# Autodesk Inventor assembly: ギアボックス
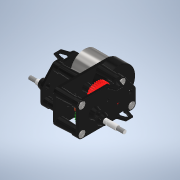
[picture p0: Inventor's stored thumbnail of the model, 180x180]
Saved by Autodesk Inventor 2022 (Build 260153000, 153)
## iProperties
Created: 2024-10
Part Number: ギアボックス
Document SubType Name: Assembly
Designer: shimizu
Author: shimizu
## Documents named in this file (11)
- C:\Users\shimizu\Documents\卒論2024\3DCAD\ギアボックス\組立図\ギアボックス.iam
- C:\Users\shimizu\Documents\卒論2024\3DCAD\ギアボックス\部品図\ギアケースA（中央）.ipt
- C:\Users\shimizu\Documents\卒論2024\3DCAD\ギアボックス\部品図\モーター.ipt
- C:\Users\shimizu\Documents\卒論2024\3DCAD\ギアボックス\部品図\ギアケースC（モーターヘッド側）.ipt
- C:\Users\shimizu\Documents\卒論2024\3DCAD\ギアボックス\部品図\ギアジョイント.ipt
- C:\Users\shimizu\Documents\卒論2024\3DCAD\ギアボックス\部品図\4mmシャフト.ipt
- C:\Users\shimizu\Documents\卒論2024\3DCAD\ギアボックス\部品図\ギアケースB（ギア側）.ipt
- C:\Users\shimizu\Documents\卒論2024\3DCAD\ギアボックス\部品図\38Tギア.ipt
- C:\Users\shimizu\Documents\卒論2024\3DCAD\ギアボックス\部品図\34T-12Tギア.iam
- C:\Users\shimizu\Documents\卒論2024\3DCAD\ギアボックス\部品図\10Tギア.ipt
- C:\Users\shimizu\Documents\卒論2024\3DCAD\ギアボックス\部品図\ねじ.ipt
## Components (17 placed, 9 different names)
1. ギアケースA（中央）:1 — メイト:1, メイト:2, メイト:3, メイト:4, メイト:5, メイト:6, メイト:7, メイト:8, メイト:9, メイト:10, メイト:29, メイト:30, メイト:31, メイト:32, 角度:2
2. モーター:1 — メイト:1, メイト:2, 角度:1, メイト:33
3. ギアケースC（モーターヘッド側）:1 — メイト:3, メイト:4, メイト:5, 角度:1, メイト:42, メイト:43, メイト:44, メイト:45, メイト:46, メイト:47
4. ギアジョイント:1 — メイト:6, メイト:7, リジッド:1, メイト:26, メイト:27
5. 4mmシャフト:1 — リジッド:1, メイト:28
6. ギアケースB（ギア側）:1 — メイト:8, メイト:9, メイト:10, メイト:34, メイト:35, メイト:36, メイト:37, メイト:38, メイト:39, メイト:40, メイト:41
7. 平歯車1:1 — メイト:26, メイト:27, メイト:28, 回転:1
8. 34T-12Tギア:1 [sub-assembly] — メイト:31, メイト:32, 回転:1, 回転:2
9. 34T-12Tギア:2 [sub-assembly] — メイト:29, メイト:30, フラッシュ:2, 回転:2, 回転:3
10. 平歯車1:2 — フラッシュ:2, メイト:33, 回転:3, 角度:2
11. JIS B 1111 M3x8:1 — メイト:34, メイト:35
12. JIS B 1111 M3x8:2 — メイト:46, メイト:47
13. JIS B 1111 M3x8:3 — メイト:36, メイト:37
14. JIS B 1111 M3x8:4 — メイト:40, メイト:41
15. JIS B 1111 M3x8:5 — メイト:38, メイト:39
16. JIS B 1111 M3x8:6 — メイト:44, メイト:45
17. JIS B 1111 M3x8:7 — メイト:42, メイト:43
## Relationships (39: Mate 32, RelateRotation 3, Angle 2, WeldJoint 1, Flush 1)
- メイト:1 [Mate]: ギアケースA（中央）:1 ↔ モーター:1
- メイト:2 [Mate]: ギアケースA（中央）:1 ↔ モーター:1
- メイト:3 [Mate]: ギアケースA（中央）:1 ↔ ギアケースC（モーターヘッド側）:1
- メイト:4 [Mate]: ギアケースA（中央）:1 ↔ ギアケースC（モーターヘッド側）:1
- メイト:5 [Mate]: ギアケースA（中央）:1 ↔ ギアケースC（モーターヘッド側）:1
- 角度:1 [Angle]: モーター:1 ↔ ギアケースC（モーターヘッド側）:1
- メイト:6 [Mate]: ギアケースA（中央）:1 ↔ ギアジョイント:1
- メイト:7 [Mate]: ギアケースA（中央）:1 ↔ ギアジョイント:1
- リジッド:1 [WeldJoint]: ギアジョイント:1 ↔ 4mmシャフト:1
- メイト:8 [Mate]: ギアケースA（中央）:1 ↔ ギアケースB（ギア側）:1
- メイト:9 [Mate]: ギアケースA（中央）:1 ↔ ギアケースB（ギア側）:1
- メイト:10 [Mate]: ギアケースA（中央）:1 ↔ ギアケースB（ギア側）:1
- メイト:26 [Mate]: ギアジョイント:1 ↔ 平歯車1:1
- メイト:27 [Mate]: ギアジョイント:1 ↔ 平歯車1:1
- メイト:28 [Mate]: 4mmシャフト:1 ↔ 平歯車1:1
- メイト:29 [Mate]: ギアケースA（中央）:1 ↔ 34T-12Tギア:2
- メイト:30 [Mate]: ギアケースA（中央）:1 ↔ 34T-12Tギア:2
- メイト:31 [Mate]: ギアケースA（中央）:1 ↔ 34T-12Tギア:1
- メイト:32 [Mate]: ギアケースA（中央）:1 ↔ 34T-12Tギア:1
- フラッシュ:2 [Flush]: 34T-12Tギア:2 ↔ 平歯車1:2
- メイト:33 [Mate]: モーター:1 ↔ 平歯車1:2
- 回転:1 [RelateRotation]: 平歯車1:1 ↔ 34T-12Tギア:1
- 回転:2 [RelateRotation]: 34T-12Tギア:1 ↔ 34T-12Tギア:2
- 回転:3 [RelateRotation]: 34T-12Tギア:2 ↔ 平歯車1:2
- 角度:2 [Angle]: ギアケースA（中央）:1 ↔ 平歯車1:2
- メイト:34 [Mate]: ギアケースB（ギア側）:1 ↔ JIS B 1111 M3x8:1
- メイト:35 [Mate]: ギアケースB（ギア側）:1 ↔ JIS B 1111 M3x8:1
- メイト:36 [Mate]: ギアケースB（ギア側）:1 ↔ JIS B 1111 M3x8:3
- メイト:37 [Mate]: ギアケースB（ギア側）:1 ↔ JIS B 1111 M3x8:3
- メイト:38 [Mate]: ギアケースB（ギア側）:1 ↔ JIS B 1111 M3x8:5
- メイト:39 [Mate]: ギアケースB（ギア側）:1 ↔ JIS B 1111 M3x8:5
- メイト:40 [Mate]: ギアケースB（ギア側）:1 ↔ JIS B 1111 M3x8:4
- メイト:41 [Mate]: ギアケースB（ギア側）:1 ↔ JIS B 1111 M3x8:4
- メイト:42 [Mate]: ギアケースC（モーターヘッド側）:1 ↔ JIS B 1111 M3x8:7
- メイト:43 [Mate]: ギアケースC（モーターヘッド側）:1 ↔ JIS B 1111 M3x8:7
- メイト:44 [Mate]: ギアケースC（モーターヘッド側）:1 ↔ JIS B 1111 M3x8:6
- メイト:45 [Mate]: ギアケースC（モーターヘッド側）:1 ↔ JIS B 1111 M3x8:6
- メイト:46 [Mate]: ギアケースC（モーターヘッド側）:1 ↔ JIS B 1111 M3x8:2
- メイト:47 [Mate]: ギアケースC（モーターヘッド側）:1 ↔ JIS B 1111 M3x8:2
